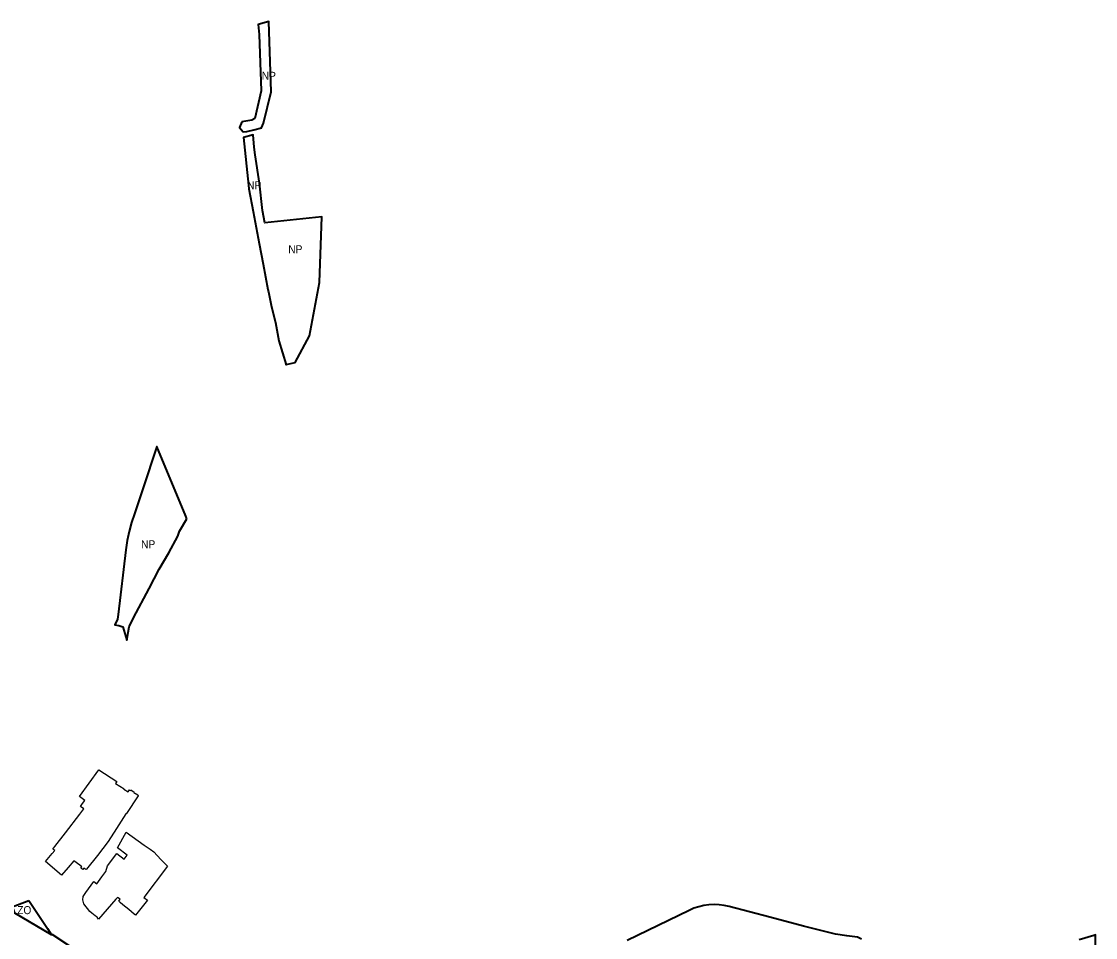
# Model space of a CAD drawing. Extents: x -650276 to -642489, y -1074311 to -1066658.
# Drawn here: x -646121 to -644510, y -1068866 to -1067493 of the extents above; entities that cross this region are included whole.
import ezdxf

# ---------------------------------------------------------------- set-up
doc = ezdxf.new("R2010")
doc.units = 0
doc.header["$LTSCALE"] = 4.8
for name, color, linetype, lineweight in [('24', 7, 'Continuous', 35), ('42', 7, 'Continuous', 35), ('48', 7, 'Continuous', 35), ('61', 7, 'Continuous', 25)]:
    doc.layers.add(name, color=color, linetype=linetype, lineweight=lineweight)
doc.layers.add('62', color=7, linetype='Continuous')
doc.layers.add('63', color=7, linetype='Continuous')

msp = doc.modelspace()

# ---------------------------------------------------------------- linework, layer by layer
at = {"layer": '24'}
msp.add_lwpolyline([(-646046.48, -1068879.92), (-646074.78, -1068861.51), (-646075.56, -1068861.95), (-646130.68, -1068829.21)], dxfattribs=at)
at = {"layer": '42'}
for points in [[(-646075.56, -1068861.95), (-646130.68, -1068829.21), (-646132.62, -1068823.54), (-646136.99, -1068820.88), (-646109.35, -1068810.23)], [(-646109.35, -1068810.23), (-646081.72, -1068852.51), (-646075.56, -1068861.95)]]:
    msp.add_lwpolyline(points, dxfattribs=at)
at = {"layer": '48'}
for points in [[(-645757.79, -1067645.206), (-645746.448, -1067597.944), (-645749.67, -1067492.54), (-645765.859, -1067496.872), (-645764.084, -1067511.925), (-645761.499, -1067596.501), (-645770.809, -1067637.786), (-645775.114, -1067640.43), (-645790.381, -1067643.17)], [(-645790.381, -1067643.17), (-645793.94, -1067651.61), (-645788.395, -1067658.038), (-645782.72, -1067657.28), (-645772.13, -1067655.13), (-645760.67, -1067652.05), (-645757.79, -1067645.206)], [(-645872.64, -1068238.08), (-645874.15, -1068234.44), (-645917.44, -1068129.99), (-645938.87, -1068193.06)], [(-645938.87, -1068193.06), (-645951.35, -1068230.61), (-645955.63, -1068243.79), (-645959.15, -1068257.17), (-645961.93, -1068270.74), (-645963.94, -1068284.44), (-645975.46, -1068381.74), (-645976.72, -1068388.53), (-645980.61, -1068397.35), (-645974.67, -1068398.28), (-645968.86, -1068400.15), (-645962.86, -1068420.15), (-645959.41, -1068400.16), (-645952.92, -1068386.53), (-645929.29, -1068342.91), (-645914.12, -1068313.54), (-645899.73, -1068289.25), (-645886.28, -1068264.22), (-645883.87, -1068256.88), (-645872.64, -1068238.08)], [(-644861.04, -1068868.43), (-644867.05, -1068865.58), (-644883.44, -1068863.56), (-644900.37, -1068860.89), (-644906.18, -1068859.57), (-644947.96, -1068848.91), (-644998.7, -1068835.48), (-645059.46, -1068819.41), (-645067.04, -1068817.76), (-645074.66, -1068816.8), (-645082.34, -1068816.52), (-645090.01, -1068816.92), (-645097.47, -1068817.98), (-645104.87, -1068819.7), (-645112.38, -1068822.16), (-645119.5, -1068825.24), (-645212.72, -1068870.49)], [(-644510.75, -1068931.16), (-644510.37, -1068861.95), (-644512.71, -1068863.06), (-644534.67, -1068869.62)]]:
    msp.add_lwpolyline(points, dxfattribs=at)
msp.add_lwpolyline([(-645750.41, -1067897.81), (-645745.86, -1067920.32), (-645739.85, -1067943.75), (-645734.61, -1067971.28), (-645723.73, -1068007.49), (-645723.785, -1068007.069), (-645710.519, -1068003.601), (-645688.88, -1067964.087), (-645673.827, -1067884.119), (-645670.064, -1067785.335), (-645755.758, -1067794.254), (-645759.32, -1067775.89), (-645763.92, -1067735.14), (-645770.39, -1067692.63), (-645771.86, -1067680.92), (-645773.23, -1067662.67), (-645787.55, -1067666.46), (-645780.39, -1067737.84), (-645779.64, -1067743.41), (-645773.04, -1067777.35), (-645764.11, -1067825.26), (-645758.47, -1067856.55), (-645751.08, -1067894.5)], close=True, dxfattribs=at)
at = {"layer": '61'}
for points in [[(-645977.65, -1068631.85), (-645979.52, -1068634.8), (-645966.82, -1068642.9), (-645967.14, -1068643.41), (-645960.63, -1068647.57), (-645958.67, -1068644.5), (-645957.36, -1068645.33), (-645956.91, -1068644.61), (-645951.87, -1068647.86), (-645952.28, -1068648.55), (-645946.37, -1068652.24), (-645945.75, -1068653.7), (-645963.17, -1068679.86), (-645964.19, -1068680.5), (-645978.4, -1068702.69), (-645990.79, -1068722.02), (-646006.77, -1068742.76), (-646023.16, -1068763.37), (-646024.22, -1068764.13), (-646027.21, -1068761.88), (-646028.77, -1068763.95), (-646031.47, -1068761.91), (-646029.91, -1068759.84), (-646033.21, -1068757.35), (-646041.889, -1068750.882), (-646050.57, -1068760.83), (-646060.78, -1068772.53), (-646084.74, -1068751.8), (-646074.61, -1068740.08), (-646070.697, -1068735.553), (-646073.6, -1068733.3), (-646070.57, -1068729.39), (-646054.6, -1068708.79), (-646033.02, -1068680.97), (-646027.29, -1068673.19), (-646032.35, -1068669.34), (-646028.98, -1068664.82), (-646025.68, -1068660.38), (-646033.67, -1068654.56), (-646004.63, -1068614.59)], [(-645966.626, -1068748.419), (-645962.14, -1068742.51), (-645976.82, -1068731.5), (-645963.52, -1068707.92), (-645936.46, -1068727.71), (-645934.95, -1068728.69), (-645927.9, -1068733.25), (-645922.38, -1068737.4), (-645911.64, -1068749.19), (-645901.71, -1068759.09), (-645937.37, -1068805.77), (-645931.74, -1068810.06), (-645949.45, -1068832.34), (-645951.53, -1068830.71), (-645955.59, -1068827.42), (-645959.81, -1068823.96), (-645964.09, -1068820.54), (-645968.55, -1068816.88), (-645972.63, -1068813.49), (-645974.79, -1068811.55), (-645972.63, -1068808.55), (-645976.52, -1068805.7), (-645979.15, -1068808.68), (-646005.18, -1068838.43), (-646007.27, -1068835.51), (-646009.97, -1068833.45), (-646012.63, -1068831.33), (-646015.29, -1068829.21), (-646017.95, -1068827.09), (-646027.13, -1068815.63), (-646028.59, -1068809.26), (-646028.24, -1068804.53), (-646023.94, -1068798.68), (-646016.36, -1068787.54), (-646012.15, -1068781.94), (-646007.68, -1068785.56), (-646000.11, -1068774.8), (-645994.29, -1068767.03), (-645991.63, -1068758.23), (-645977.81, -1068739.99)]]:
    msp.add_lwpolyline(points, close=True, dxfattribs=at)

# ---------------------------------------------------------------- texts
at = {"layer": '62', "width": 0.95}
for s, p in [('NP', (-645782.298, -1067744)), ('NP', (-645720.583, -1067840.041)), ('NP', (-645941.298, -1068282.326)), ('ZO', (-646127.027, -1068830.859))]:
    msp.add_text(s, height=12, dxfattribs=at).set_placement(p)
at = {"layer": '63', "width": 0.95}
msp.add_text('NP', height=12, dxfattribs=at).set_placement((-645760.298, -1067580))

doc.saveas('drawing.dxf')
